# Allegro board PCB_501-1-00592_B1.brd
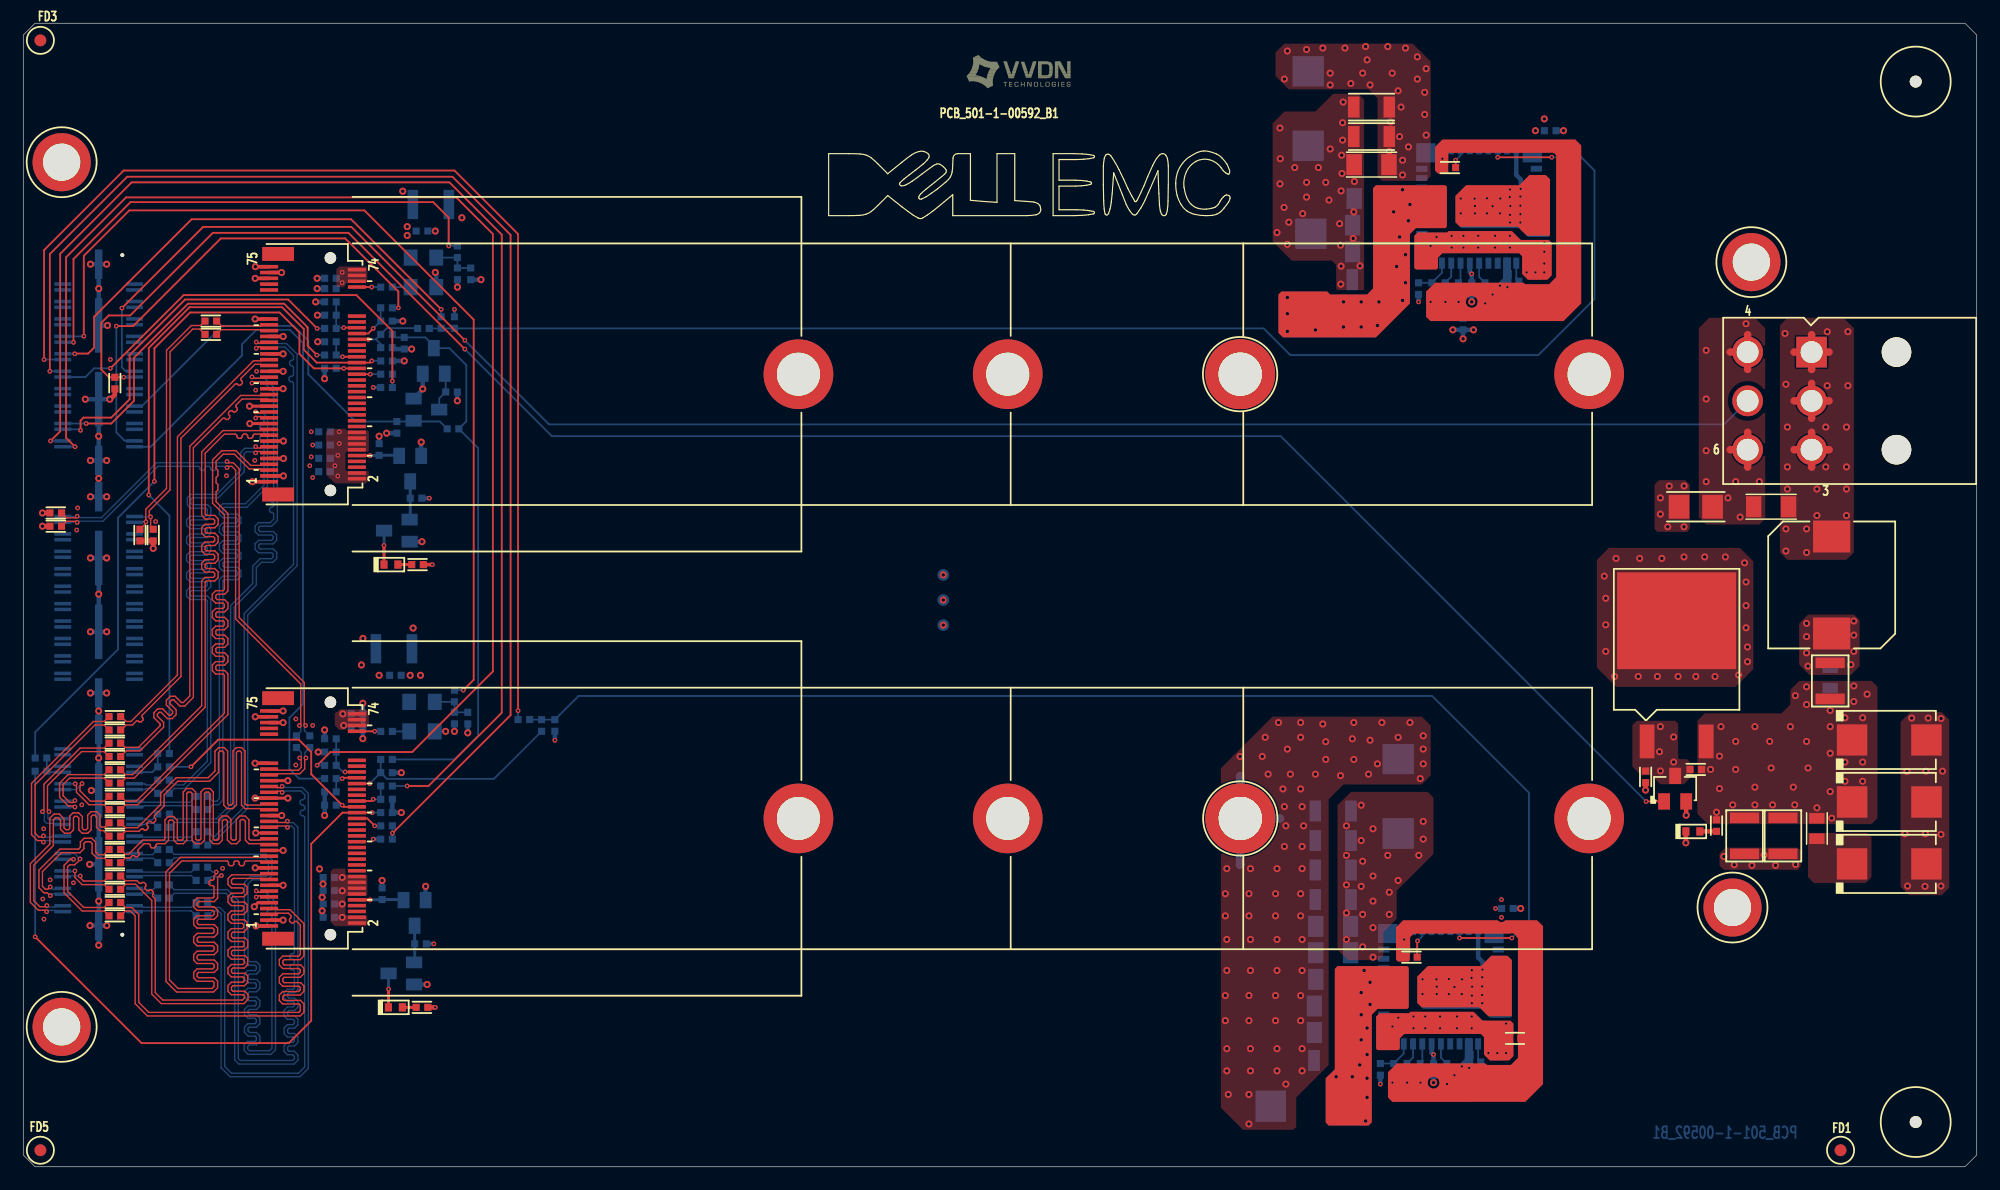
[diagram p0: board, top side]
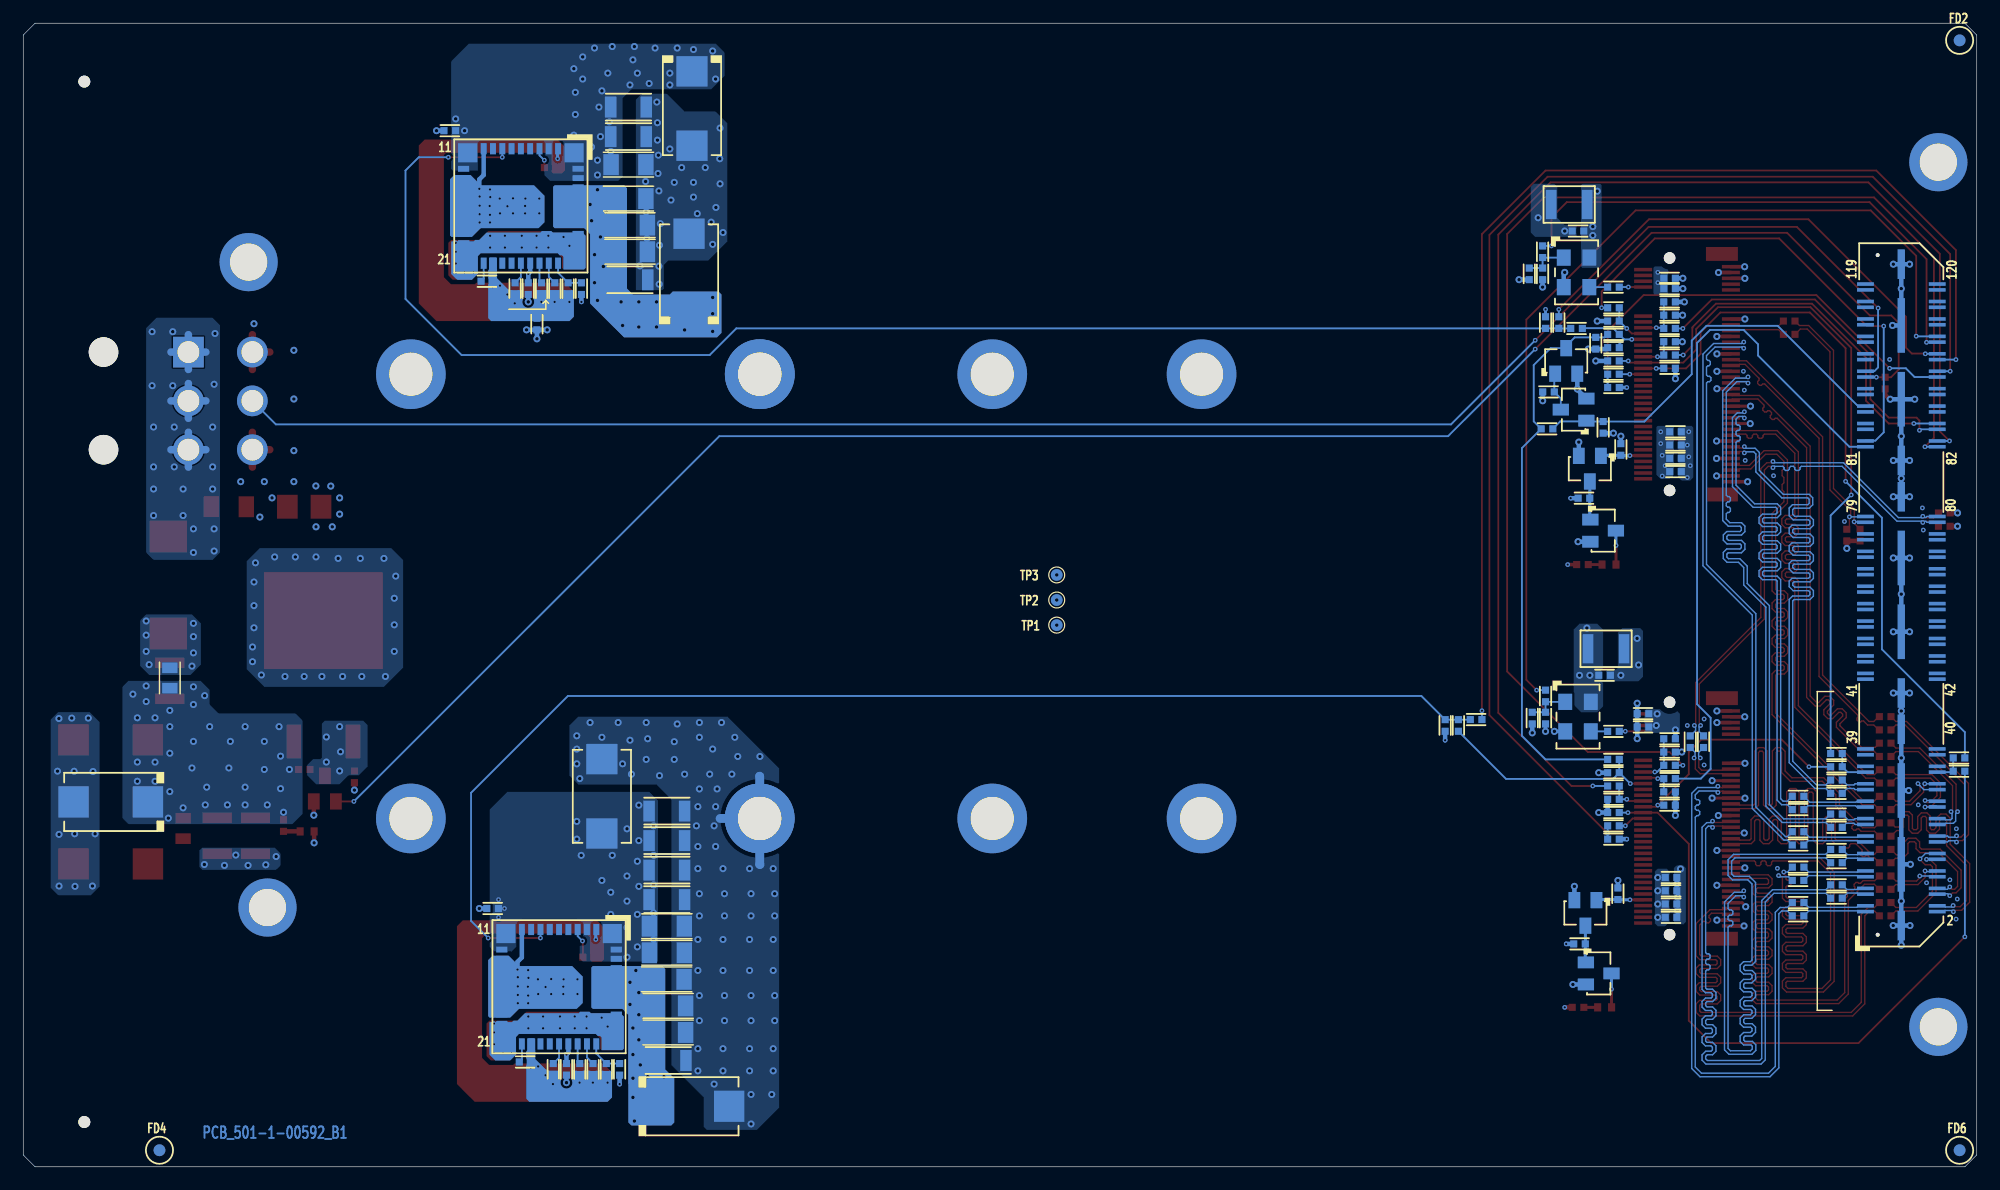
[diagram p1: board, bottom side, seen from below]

Outline 168 x 98.4 mm; copper layers: TOP, GROUND, POWER, BOTTOM. Coordinates in mm from the lower left corner of the outline.
Outline path: 0,97.38 1.02,98.4 166.98,98.4 168,97.38 168,1.02 166.98,0 1.02,0 0,1.02 0,97.38

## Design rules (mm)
constraint set DEFAULT: min track width 0.152, pair gap 0.178
net group CLK0_N: nets CLK0_N PCIE_CG1_HSMC_CLK0_N
net group CLK0_P: nets CLK0_P PCIE_CG1_HSMC_CLK0_P
net group CLK1_N: nets CLK1_N PCIE_CG1_HSMC_CLK1_N
net group CLK1_P: nets CLK1_P PCIE_CG1_HSMC_CLK1_P
net group PCIE_NVM_TX0_N: nets C_PCIE_NVM_TX0_N
net group PCIE_NVM_TX0_P: nets C_PCIE_NVM_TX0_P
net group PCIE_NVM_TX1_N: nets C_PCIE_NVM_TX1_N
net group PCIE_NVM_TX1_P: nets C_PCIE_NVM_TX1_P
net group PCIE_NVM_TX2_N: nets C_PCIE_NVM_TX2_N
net group PCIE_NVM_TX2_P: nets C_PCIE_NVM_TX2_P
net group PCIE_NVM_TX3_N: nets C_PCIE_NVM_TX3_N
net group PCIE_NVM_TX3_P: nets C_PCIE_NVM_TX3_P
net group PCIE_NVM_TX4_N: nets C_PCIE_NVM_TX4_N
net group PCIE_NVM_TX4_P: nets C_PCIE_NVM_TX4_P
net group PCIE_NVM_TX5_N: nets C_PCIE_NVM_TX5_N
net group PCIE_NVM_TX5_P: nets C_PCIE_NVM_TX5_P
net group PCIE_NVM_TX6_N: nets C_PCIE_NVM_TX6_N
net group PCIE_NVM_TX6_P: nets C_PCIE_NVM_TX6_P
net group PCIE_NVM_TX7_N: nets C_PCIE_NVM_TX7_N
net group PCIE_NVM_TX7_P: nets C_PCIE_NVM_TX7_P

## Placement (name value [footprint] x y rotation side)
C17  22uF  [1210]  31.88 44.58 180 bottom
C18  0.1uF  [0402]  32 42.29 180 bottom
C19  22uF  [1210]  35.05 82.8 0 bottom
C20  0.1uF  [0402]  34.29 80.52 0 bottom
C21  100uF  [TCAP_CASED]  160.48 36.73 0 top
C22  22uF  [1210]  148.03 28.47 270 top
C23  22uF  [1210]  151.33 28.47 270 top
C24  100uF  [TCAP_CASED]  160.48 31.39 0 top
C25  100uF  [TCAP_CASED]  160.48 31.39 0 bottom
C26  4.7uF  [1206]  112.65 18.41 180 bottom
C27  47uF  [CAP_1206]  112.65 28.07 180 bottom
C28  47uF  [CAP_1206]  112.65 30.61 180 bottom
C29  47uF  [CAP_1206]  112.65 25.53 180 bottom
C30  4.7uF  [1206]  112.65 20.7 180 bottom
C32  47uF  [CAP_1206]  112.65 22.99 180 bottom
C34  4.7uF  [1206]  112.67 16.13 180 bottom
C36  100uF  [1206]  112.54 13.84 180 bottom
C37  100uF  [1206]  112.54 11.56 180 bottom
C38  220uF  [TCAP_CASED]  110.49 5.21 180 bottom
C39  3300pF  [0402]  120.14 8.38 90 bottom
C40  0.1uF  [0402]  127.64 22.23 0 bottom
C41  0.1uF  [0402]  121.29 8.38 270 bottom
C42  47uF  [CAP_1206]  112.54 9.14 180 bottom
C43  100uF  [TCAP_CASEE]  118.24 31.88 90 bottom
C44  4.7uF  [1206]  115.95 86.23 180 top
C45  100uF  [TCAP_CASEE]  110.49 91.06 270 bottom
C46  47uF  [CAP_1206]  115.95 91.19 180 top
C47  47uF  [CAP_1206]  115.95 88.65 180 top
C48  47uF  [CAP_1206]  115.95 91.19 180 bottom
C49  47uF  [CAP_1206]  115.95 88.65 180 bottom
C50  4.7uF  [1206]  115.95 86.23 180 bottom
C51  0.1uF  [0402]  131.32 89.15 0 bottom
C52  0.1uF  [0402]  124.57 75.56 270 bottom
C53  4.7uF  [1206]  115.95 83.31 180 bottom
C54  47uF  [CAP_1206]  115.82 76.33 180 bottom
C55  100uF  [1206]  115.82 78.74 180 bottom
C56  100uF  [1206]  115.82 81.03 180 bottom
C57  220uF  [TCAP_CASED]  110.74 77.09 90 bottom
C58  3300pF  [0402]  123.43 75.56 90 bottom
C59  0.1uF  [0402]  28.7 37.85 0 bottom
C61  0.1uF  [0402]  25.91 60.96 180 bottom
C63  0.1uF  [0402]  26.29 22.61 180 bottom
C64  0.1uF  [0402]  26.29 23.75 180 bottom
C65  0.1uF  [0402]  26.29 24.89 180 bottom
C67  0.1uF  [0402]  25.91 59.82 180 bottom
C68  0.1uF  [0402]  25.91 62.1 180 bottom
C69  0.1uF  [0402]  26.42 75.56 180 bottom
C71  4.7uF  [0402]  26.29 21.46 180 bottom
C72  4.7uF  [0402]  28.7 38.99 0 bottom
C73  4.7uF  [0402]  25.91 63.25 180 bottom
C74  4.7uF  [0402]  26.42 76.45 180 bottom
C75  4.7uF  [1206]  150.32 56.79 180 top
C76  100uF  [TCAP_CASED]  160.48 26.06 0 top
D4  G  [LED-0402]  143.59 28.85 180 top
D5  G  [LED-0402]  32 13.72 180 top
D7  G  [LED-0402]  31.62 51.82 180 top
FB1  50E  [FBEAD-1206]  143.84 56.79 0 top
FD1  Local  [LFD40_80]  156.29 1.42 0 top
FD2  Local  [LFD40_80]  1.47 96.93 180 bottom
FD3  Local  [LFD40_80]  1.47 96.93 0 top
FD4  Local  [LFD40_80]  156.29 1.42 180 bottom
FD5  Local  [LFD40_80]  1.47 1.42 0 top
FD6  Local  [LFD40_80]  1.47 1.42 180 bottom
J1  CON_HSMCx3  [CON_HMSC_1X1M_132L_0P5_SM_ST]  6.49 49.21 90 bottom
J4  CON_B2C_2X3  [CON_B2C_2X3M_4P2_TH_RA_A]  153.8 70.1 90 top
J7  CON_NGFF-M  [CON_NGFF_75F_0P5_SM_RA_CST_B_A1]  26.42 29.97 90 top
J8  CON_NGFF-M  [CON_NGFF_75F_0P5_SM_RA_CST_B_A1]  26.42 68.2 90 top
L1  2.2uH  [IND2_8P34_10P1X10P1]  155.52 50.06 90 top
M1  LMZ31710  [BQFN42_0P8_10X10_EP]  121.92 15.49 270 bottom
M2  LMZ31710  [BQFN42_0P8_10X10_EP]  125.2 82.68 270 bottom
MECH1  MECH_SPACER  [MECH-M2P5_RAD3P7_C_A1]  104.67 29.97 0 top
MECH2  MECH_SPACER  [MECH-M2P5_RAD3P7_C_A1]  104.65 68.2 0 top
MH1  128MILS  [MH197D128N]  162.75 3.85 0 top
MH2  126MILS  [MH197D126]  147 22.31 0 top
MH3  126MILS  [MH197D126]  3.3 86.44 0 top
MH4  128MILS  [MH197D128N]  162.75 93.38 0 top
MH5  126MILS  [MH197D126]  3.3 12.04 0 top
MH6  126MILS  [MH197D126]  148.62 77.84 0 top
NOREF  -  []  21.14 20.72 90 top
NOREF#2  -  []  84.67 29.97 0 top
NOREF#3  -  []  21.14 34.72 90 top
NOREF#4  -  []  104.67 29.97 0 top
NOREF#5  -  []  -95.76 138.68 0 top
NOREF#6  -  []  21.14 72.95 90 top
NOREF#7  -  []  21.14 58.95 90 top
NOREF#8  -  []  21.14 58.95 90 top
NOREF#9  -  []  21.14 37.22 90 top
NOREF#10  -  []  26.42 58.2 90 top
NOREF#11  -  []  21.14 27.72 90 top
NOREF#12  -  []  21.14 20.72 90 top
NOREF#13  -  []  1.47 1.42 0 top
NOREF#14  -  []  21.14 75.45 90 top
NOREF#15  -  []  21.14 77.45 0 top
NOREF#16  -  []  104.67 68.2 0 top
NOREF#17  -  []  21.92 57.85 90 top
NOREF#18  -  []  21.14 39.22 0 top
NOREF#19  -  []  84.67 68.2 0 top
NOREF#20  -  []  66.67 29.97 90 top
NOREF#21  -  []  21.14 65.95 90 top
NOREF#22  -  []  66.67 29.97 0 top
NOREF#23  -  []  166.98 0 90 top
NOREF#24  -  []  26.42 19.97 90 top
NOREF#25  -  []  21.92 19.62 90 top
NOREF#26  -  []  66.67 68.2 90 top
NOREF#27  -  []  66.67 68.2 0 top
NOREF#28  -  []  0 97.38 0 top
Q1  SUM110P06-08L  [TO263-3L_5P08_10P29X9P65_A]  142.19 36.6 0 top
Q2  FDV301N  [SOT23-3L_1P9_3P12X1P5]  142.06 32.54 0 top
Q3  FDV301N  [SOT23-3L_1P9_3P12X1P5]  34.67 65.15 90 bottom
Q4  FDV301N  [SOT23-3L_1P9_3P12X1P5]  35.31 69.34 180 bottom
Q5  FDV301N  [SOT23-3L_1P9_3P12X1P5]  32.51 16.64 270 bottom
Q6  FDV301N  [SOT23-3L_1P9_3P12X1P5]  33.66 21.84 0 bottom
Q7  FDV301N  [SOT23-3L_1P9_3P12X1P5]  32.13 54.74 270 bottom
Q8  FDV301N  [SOT23-3L_1P9_3P12X1P5]  33.27 60.07 0 bottom
R1  0E  [0402]  7.87 25.02 180 top
R2  0E  [0402]  7.87 29.59 180 top
R3  0E  [0402]  7.87 28.45 180 top
R4  0E  [0402]  7.87 27.3 180 top
R5  0E  [0402]  7.87 26.16 180 top
R6  0E  [0402]  7.87 23.88 180 top
R7  0E  [0402]  7.87 21.59 180 top
R8  0E  [0402]  7.87 22.73 180 top
R9  0E  [0402]  7.87 38.74 180 top
R10  0E  [0402]  7.87 37.59 180 top
R11  0E  [0402]  7.87 36.45 180 top
R12  0E  [0402]  7.87 35.31 180 top
R13  0E  [0402]  7.87 34.16 180 top
R14  0E  [0402]  7.87 33.02 180 top
R15  0E  [0402]  7.87 31.88 180 top
R16  0E  [0402]  7.87 30.73 180 top
R17  0E  [0402]  1.52 34.04 180 bottom
R18  0E  [0402]  12.06 34.42 0 bottom
R19  0E  [0402_HD]  1.52 35.18 180 bottom
R20  0E  [0402]  12.06 35.56 0 bottom
R21  49.9E  [0402]  11.18 54.36 270 top
R22  49.9E  [0402]  2.79 56.26 180 top
R23  49.9E  [0402]  10.03 54.36 270 top
R24  49.9E  [0402]  2.79 55.12 180 top
R25  0E  [0402]  31.24 35.05 180 bottom
R26  0E  [0402]  31.24 71.63 180 bottom
R29  10K  [0402]  31.24 30.48 0 bottom
R30  10K  [0402]  26.42 31.11 180 bottom
R31  10K  [0402]  31.24 31.62 0 bottom
R32  10K  [0402]  31.24 33.91 0 bottom
R33  10K  [0402]  26.42 32.26 180 bottom
R34  0E  [0402]  31.24 32.77 180 bottom
R35  4.75K  [0402]  26.42 36.83 180 bottom
R36  0E  [0402]  26.42 33.4 0 bottom
R37  0E  [0402]  24.64 36.58 90 bottom
R38  0E  [0402]  26.42 34.54 0 bottom
R39  10K  [0402]  26.42 35.69 0 bottom
R40  0E  [0402]  23.49 36.58 90 bottom
R41  10K  [0402]  38.23 38.61 270 bottom
R42  10K  [0402]  37.08 38.61 90 bottom
R45  10K  [0402]  26.42 68.71 180 bottom
R46  10K  [0402]  31.24 69.34 0 bottom
R47  10K  [0402]  26.42 70.99 180 bottom
R48  10K  [0402]  31.24 70.48 0 bottom
R49  10K  [0402]  31.24 72.77 0 bottom
R50  0E  [0402]  26.42 69.85 0 bottom
R51  4.75K  [0402]  26.42 73.28 180 bottom
R52  0E  [0402]  31.24 73.91 180 bottom
R53  0E  [0402]  16.13 71.63 180 top
R54  0E  [0402]  26.42 72.14 0 bottom
R55  0E  [0402]  16.13 72.77 180 top
R56  10K  [0402]  26.42 74.42 0 bottom
R57  10K  [0402]  38.48 76.83 270 bottom
R58  10K  [0402]  37.34 76.83 90 bottom
R59  1K  [0402]  143.84 34.19 0 top
R60  1K  [0402]  145.62 29.36 90 top
R61  1K  [0402]  139.52 33.55 90 top
R62  10K  [0402]  7.87 67.44 90 top
R63  0E  [0402]  119 8.38 90 bottom
R64  316E  [0402]  122.42 8.38 270 bottom
R66  10K  [0402]  45.72 37.97 270 bottom
R67  0E  [0402]  43.05 38.48 180 bottom
R68  0E  [0402]  37.08 40.51 90 bottom
R69  0E  [0402]  37.34 78.74 90 bottom
R70  0E  [0402]  31.24 29.34 180 bottom
R71  0E  [0402]  31.24 68.2 180 bottom
R72  0E  [0402]  31.24 37.47 180 bottom
R73  0E  [0402]  31.24 75.69 180 bottom
R74  10K  [0402]  32.13 63.63 90 bottom
R75  10K  [0402]  36.83 66.67 0 bottom
R76  10K  [0402]  32.77 70.87 270 bottom
R77  0E  [0402]  36.96 63.5 0 bottom
R78  0E  [0402]  15.37 21.59 0 bottom
R79  0E  [0402]  15.36 22.73 0 bottom
R80  0E  [0402]  12.06 23.11 0 bottom
R81  0E  [0402]  12.06 24.26 0 bottom
R82  0E  [0402]  15.37 24.64 0 bottom
R83  0E  [0402]  15.36 25.78 0 bottom
R84  0E  [0402]  12.06 26.16 0 bottom
R85  0E  [0402]  12.06 27.3 0 bottom
R86  0E  [0402]  15.37 27.69 0 bottom
R87  0E  [0402]  15.37 28.83 0 bottom
R88  0E  [0402]  12.06 29.21 0 bottom
R89  0E  [0402]  12.06 30.35 0 bottom
R90  0E  [0402]  15.37 30.73 0 bottom
R91  0E  [0402]  15.37 31.88 0 bottom
R92  0E  [0402]  12.06 32.13 0 bottom
R93  0E  [0402]  12.06 33.27 0 bottom
R94  69.8E  [0402]  34.29 13.72 0 top
R95  10K  [0402]  34.16 19.18 0 bottom
R98  10K  [0402]  30.86 23.5 270 bottom
R99  10K  [0402]  31.24 28.19 180 bottom
R100  69.8E  [0402]  33.91 51.82 0 top
R101  10K  [0402]  33.78 57.53 0 bottom
R102  10K  [0402]  30.61 61.72 270 bottom
R103  10K  [0402]  31.24 67.06 180 bottom
R105  90.9K  [0402]  124.84 9.02 0 bottom
R106  9.31K  [0402]  117.86 8.38 90 bottom
R107  68.1K  [0402]  116.71 8.38 270 bottom
R108  10K  [0402]  119.38 18.03 180 top
R109  68.1K  [0402]  120 75.56 270 bottom
R110  316E  [0402]  125.7 75.56 270 bottom
R111  9.31K  [0402]  121.14 75.56 90 bottom
R112  0E  [0402]  122.28 75.56 90 bottom
R113  10K  [0402]  122.68 85.98 180 top
R114  10K  [0402]  37.08 72.64 90 bottom
R115  90.9K  [0402]  128.12 76.2 0 bottom
R116  0E  [0402]  123.83 72.52 90 bottom
R117  0E  [0402]  128.29 11.05 0 top
R118  0E  [0402]  35.94 72.64 90 bottom
R119  0E  [0402]  44.58 37.97 270 bottom
R120  0E  [0402]  34.42 72.14 180 bottom
R121  0E  [0805]  154.25 29.11 90 top
R122  0E  [0805]  155.4 42.06 90 bottom
R123  3.3E  [1210]  155.4 41.81 90 top
TP1  SMD  [TP40_SMD]  79.12 46.61 180 bottom
TP2  SMD  [TP40_SMD]  79.12 48.77 180 bottom
TP3  SMD  [TP40_SMD]  79.12 50.93 180 bottom
Y3  32.768KHz  [OSC4_2P2_5X3P2_1P35]  34.29 38.74 270 bottom
Y4  32.768KHz  [OSC4_2P2_5X3P2_1P35]  34.42 76.96 270 bottom

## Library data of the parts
C17-C20 C22 C23 C26-C30 C32 C34 C36 C37 C39-C42 C44 C46-C56 C58 C59 C61 C63-C65 C67-C69 C71-C75 = CAP_NP
C21 C24 C25 C38 C43 C45 C57 C76 = CAP_POL
D4 D5 D7 = DIODE_LED_A
FB1 = FER_BEAD
FD1-FD6 = MECH_FID_L
J1 = CONN_HSMCX3_132P_HETERO
J4 = CONN_B2C_2X3_6P_A
J7 J8 = CONN_NGFF-M_1X67_73P_CUST_A1
L1 = IND_CORE_B
M1 M2 = MODPWR_DC-DC_1OUT_42P
MECH1 MECH2 = MECH_SPACER
MH1 MH4 = MECH_MH_NPL
MH2 MH3 MH5 MH6 = MECH_MH_PL
Q1 = TRANS_PMOS-ENX1_3P_A
Q2-Q8 = TRANS_NMOS-ENX1_3P_I
R1-R16 R37 R40 R53 R55 R78-R93 = RES: signal model: RES_0402_0E_0E
R17-R26 R29-R36 R38 R39 R41 R42 R45-R52 R54 R56-R64 R66-R77 R94 R95 R98-R103 R105-R123 = RES
TP1-TP3 = TEST_POINT_SMD
Y3 Y4 = OSC_4P_A

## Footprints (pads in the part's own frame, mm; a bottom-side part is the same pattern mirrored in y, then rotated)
0402
  rect 0.61x0.61 smd: 1(-0.5,0) 2(0.5,0)
0402_HD
  rect 0.61x0.61 smd: 1(-0.5,0) 2(0.5,0)
0805
  rect 0.914x1.321 smd: 1(-0.875,0) 2(0.875,0)
1206
  rect 1.321x1.803 smd: 1(-1.5,0) 2(1.5,0)
1210
  rect 0.914x2.515 smd: 1(-1.55,0) 2(1.55,0)
BQFN42_0P8_10X10_EP
  rect 1.651x1.651 smd: 1(-4.575,4.575) 11(-4.575,-4.575) 21(4.575,-4.575) 31(4.575,4.575)
  rect 0.965x0.508 smd: 2(-4.925,3.2) 3(-4.925,2.4) 4(-4.925,1.6) 5(-4.925,0.8) 6(-4.925,0) 7(-4.925,-0.8) 8(-4.925,-1.6) 9(-4.925,-2.4) 10(-4.925,-3.2) 22(4.925,-3.2) 23(4.925,-2.4) 24(4.925,-1.6) 25(4.925,-0.8) 26(4.925,0) 27(4.925,0.8) 28(4.925,1.6) 29(4.925,2.4) 30(4.925,3.2)
  rect 0.508x0.965 smd: 12(-3.2,-4.925) 13(-2.4,-4.925) 14(-1.6,-4.925) 15(-0.8,-4.925) 16(0,-4.925) 17(0.8,-4.925) 18(1.6,-4.925) 19(2.4,-4.925) 20(3.2,-4.925) 32(3.2,4.925) 33(2.4,4.925) 34(1.6,4.925) 35(0.8,4.925) 36(0,4.925) 37(-0.8,4.925) 38(-1.6,4.925) 39(-2.4,4.925) 40(-3.2,4.925)
  rect 3.302x1.397 smd: 41(0,3.55)
  custom 0.822x0.822 smd: 42(0,-1.225)
CAP_1206
  rect 0.991x1.803 smd: 1(-1.53,0) 2(1.53,0)
CON_B2C_2X3M_4P2_TH_RA_A
  round 2.54 hole 3.073 unplated: (-8.4,-7.3) (0,-7.3)
  rect 2.642x2.642 hole 1.88: 1(0,0)
  round 2.642 hole 1.88: 2(-4.2,0) 3(-8.4,0) 4(0,5.5) 5(-4.2,5.5) 6(-8.4,5.5)
CON_HMSC_1X1M_132L_0P5_SM_ST
  round 0.33 hole 1.092 unplated: (-29.245,2.03) (29.235,2.03)
  rect 0.305x1.448 smd: 1(-27.255,3.08) 2(-27.255,-3.09) 3(-26.755,3.08) 4(-26.755,-3.09) 5(-25.755,3.08) 6(-25.755,-3.09) 7(-25.255,3.08) 8(-25.255,-3.09) 9(-24.255,3.08) 10(-24.255,-3.09) 11(-23.755,3.08) 12(-23.755,-3.09) 13(-22.755,3.08) 14(-22.755,-3.09) 15(-22.255,3.08) 16(-22.255,-3.09) 17(-21.255,3.08) 18(-21.255,-3.09) 19(-20.755,3.08) 20(-20.755,-3.09) 21(-19.755,3.08) 22(-19.755,-3.09) 23(-19.255,3.08) 24(-19.255,-3.09) 25(-18.255,3.08) 26(-18.255,-3.09) 27(-17.755,3.08) 28(-17.755,-3.09) 29(-16.755,3.08) 30(-16.755,-3.09) 31(-16.255,3.08) 32(-16.255,-3.09) 33(-15.255,3.08) 34(-15.255,-3.09) 35(-14.755,3.08) 36(-14.755,-3.09) 37(-13.755,3.08) 38(-13.755,-3.09) 39(-13.255,3.08) 40(-13.255,-3.09) 41(-7.255,3.08) 42(-7.255,-3.09) 43(-6.755,3.08) 44(-6.755,-3.09) 45(-5.755,3.08) 46(-5.755,-3.09) 47(-5.255,3.08) 48(-5.255,-3.09) 49(-4.255,3.08) 50(-4.255,-3.09) 51(-3.755,3.08) 52(-3.755,-3.09) 53(-2.755,3.08) 54(-2.755,-3.09) 55(-2.255,3.08) 56(-2.255,-3.09) 57(-1.255,3.08) 58(-1.255,-3.09) 59(-0.755,3.08) 60(-0.755,-3.09) 61(0.245,3.08) 62(0.245,-3.09) 63(0.745,3.08) 64(0.745,-3.09) 65(1.745,3.08) 66(1.745,-3.09) 67(2.245,3.08) 68(2.245,-3.09) 69(3.245,3.08) 70(3.245,-3.09) 71(3.745,3.08) 72(3.745,-3.09) 73(4.745,3.08) 74(4.745,-3.09) 75(5.245,3.08) 76(5.245,-3.09) 77(6.245,3.08) 78(6.245,-3.09) 79(6.745,3.08) 80(6.745,-3.09) 81(12.745,3.08) 82(12.745,-3.09) 83(13.245,3.08) 84(13.245,-3.09) 85(14.245,3.08) 86(14.245,-3.09) 87(14.745,3.08) 88(14.745,-3.09) 89(15.745,3.08) 90(15.745,-3.09) 91(16.245,3.08) 92(16.245,-3.09) 93(17.245,3.08) 94(17.245,-3.09) 95(17.745,3.08) 96(17.745,-3.09) 97(18.745,3.08) 98(18.745,-3.09) 99(19.245,3.08) 100(19.245,-3.09) 101(20.245,3.08) 102(20.245,-3.09) 103(20.745,3.08) 104(20.745,-3.09) 105(21.745,3.08) 106(21.745,-3.09) 107(22.245,3.08) 108(22.245,-3.09) 109(23.245,3.08) 110(23.245,-3.09) 111(23.745,3.08) 112(23.745,-3.09) 113(24.745,3.08) 114(24.745,-3.09) 115(25.245,3.08) 116(25.245,-3.09) 117(26.245,3.08) 118(26.245,-3.09) 119(26.745,3.08) 120(26.745,-3.09)
  rect 2.54x0.635 smd: 121(-28.455,0) 124(-11.565,0) 125(-8.445,0) 128(8.445,0) 129(11.565,0) 132(28.455,0)
  rect 4.699x0.635 smd: 122(-23.185,0) 123(-16.835,0) 126(-3.175,0) 127(3.175,0) 130(16.835,0) 131(23.185,0)
CON_NGFF_75F_0P5_SM_RA_CST_B_A1
  round 0.991 hole 1.118 unplated: (-10,0)
  round 0.991 hole 1.6 unplated: (10,0)
  rect 0.305x1.549 smd: 1(-9.25,5.275) 2(-9,-2.275) 3(-8.75,5.275) 4(-8.5,-2.275) 5(-8.25,5.275) 6(-8,-2.275) 7(-7.75,5.275) 8(-7.5,-2.275) 9(-7.25,5.275) 10(-7,-2.275) 11(-6.75,5.275) 12(-6.5,-2.275) 13(-6.25,5.275) 14(-6,-2.275) 15(-5.75,5.275) 16(-5.5,-2.275) 17(-5.25,5.275) 18(-5,-2.275) 19(-4.75,5.275) 20(-4.5,-2.275) 21(-4.25,5.275) 22(-4,-2.275) 23(-3.75,5.275) 24(-3.5,-2.275) 25(-3.25,5.275) 26(-3,-2.275) 27(-2.75,5.275) 28(-2.5,-2.275) 29(-2.25,5.275) 30(-2,-2.275) 31(-1.75,5.275) 32(-1.5,-2.275) 33(-1.25,5.275) 34(-1,-2.275) 35(-0.75,5.275) 36(-0.5,-2.275) 37(-0.25,5.275) 38(0,-2.275) 39(0.25,5.275) 40(0.5,-2.275) 41(0.75,5.275) 42(1,-2.275) 43(1.25,5.275) 44(1.5,-2.275) 45(1.75,5.275) 46(2,-2.275) 47(2.25,5.275) 48(2.5,-2.275) 49(2.75,5.275) 50(3,-2.275) 51(3.25,5.275) 52(3.5,-2.275) 53(3.75,5.275) 54(4,-2.275) 55(4.25,5.275) 56(4.5,-2.275) 57(4.75,5.275) 58(5,-2.275) 67(7.25,5.275) 68(7.5,-2.275) 69(7.75,5.275) 70(8,-2.275) 71(8.25,5.275) 72(8.5,-2.275) 73(8.75,5.275) 74(9,-2.275) 75(9.25,5.275)
  rect 1.194x2.743 smd: M1(-10.35,4.5) M2(10.35,4.5)
  round 5.994 hole 3.708: M3(0,-40.25) M4(0,-58.25) M5(0,-78.25) M6(0,-108.25)
FBEAD-1206
  rect 1.778x2.057 smd: 1(-1.445,0) 2(1.445,0)
IND2_8P34_10P1X10P1
  rect 2.743x3.2 smd: 1(-4.172,0) 2(4.172,0)
LED-0402
  rect 0.61x0.711 smd: 1(-0.6,0) 2(0.6,0)
LFD40_80
  round 1.016 smd: 1(0,0)
MECH-M2P5_RAD3P7_C_A1
  round 5.994 hole 3.708: 1(0,0)
MH197D126
  round 5.004 hole 3.2: 1(0,0)
MH197D128N
  round 1.016 hole 3.251: 1(0,0)
OSC4_2P2_5X3P2_1P35
  rect 1.397x1.194 smd: 1(-1.27,-1.1) 2(1.27,-1.1) 3(1.27,1.1) 4(-1.27,1.1)
SOT23-3L_1P9_3P12X1P5
  rect 1.016x1.397 smd: 1(-0.95,-1.1) 2(0.95,-1.1) 3(0,1.1)
TCAP_CASED
  rect 2.616x2.692 smd: 1(-3.2,0) 2(3.2,0)
TCAP_CASEE
  rect 2.616x2.692 smd: 1(-3.2,0) 2(3.2,0)
TO263-3L_5P08_10P29X9P65_A
  rect 1.27x2.896 smd: 1(-2.54,0) 3(2.54,0)
  rect 10.236x8.331 smd: 4(0,10.387)
TP40_SMD
  round 1.016 smd: 1(0,0)

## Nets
GND_POWER: C17.2 C18.2 C19.2 C20.2 C21.2(CATHODE) C22.2 C23.2 C24.2(CATHODE) C25.2(CATHODE) C26.2 C27.2 C28.2 C29.2 C30.2 C32.2 C34.2 C36.2 C37.2 C38.2(CATHODE) C40.2 C41.2 C42.2 C43.2(CATHODE) C44.2 C45.2(CATHODE) C46.2 C47.2 C48.2 C49.2 C50.2 C51.2 C52.2 C53.2 C54.2 C55.2 C56.2 C57.2(CATHODE) C59.2 C61.2 C63.2 C64.2 C65.2 C67.2 C68.2 C69.2 C71.2 C72.2 C73.2 C74.2 C76.2(CATHODE) D4.2(K) FB1.1 J1.121 J1.122 J1.123 J1.124 J1.125 J1.126 J1.127 J1.128 J1.129 J1.130 J1.131 J1.132(B3_PWR4) J7.1 J7.3 J7.9 J7.15 J7.21 J7.27 J7.33 J7.39 J7.45 J7.51 J7.57 J7.71 J7.73 J7.75 J7.M3 J7.M4 J7.M5 J7.M6 J8.1 J8.3 J8.9 J8.15 J8.21 J8.27 J8.33 J8.39 J8.45 J8.51 J8.57 J8.71 J8.73 J8.75 J8.M3 J8.M4 J8.M5 J8.M6 M1.20 M1.21 M1.31 M1.32 M1.33 M2.20 M2.21 M2.31 M2.32 M2.33 MH2.1 MH3.1 MH5.1 MH6.1 Q2.2(SOURCE) Q3.2(SOURCE) Q4.2(SOURCE) Q5.2(SOURCE) Q6.2(SOURCE) Q7.2(SOURCE) Q8.2(SOURCE) R21.2 R22.2 R23.2 R24.2 R39.1 R42.1 R56.1 R58.1 R61.1 R62.1 R74.1 R98.1 R102.1 R116.1 R117.1 TP2.1 Y3.2 Y4.2
GND_POWER_AUX: C75.2 FB1.2 J4.4 J4.6
SGND1: C39.1 M1.2 M1.23 R63.1 R64.2 R105.1 R106.1 R108.2 R117.2
SGND2: C58.1 M2.2 M2.23 R110.2 R111.1 R112.1 R113.2 R115.1 R116.2
VCC_3V3_A: C17.1 C18.1 C34.1 C36.1 C37.1 C38.1 C41.1 C42.1 C59.1 C63.1 C64.1 C65.1 C71.1 C72.1 J7.2 J7.4 J7.12 J7.14 J7.16 J7.18 J7.70 J7.72 J7.74 M1.27 M1.34 M1.35 M1.36 M1.37 M1.38 M1.41(VOUT6) R29.2 R30.2 R31.2 R32.2 R33.2 R35.2 R41.2 R66.2 R94.2 R95.2 R99.2 TP1.1 Y3.4(VDD)
VCC_3V3_B: C19.1 C20.1 C52.1 C53.1 C54.1 C55.1 C56.1 C57.1 C61.1 C67.1 C68.1 C69.1 C73.1 C74.1 J8.2 J8.4 J8.12 J8.14 J8.16 J8.18 J8.70 J8.72 J8.74 M2.27 M2.34 M2.35 M2.36 M2.37 M2.38 M2.41(VOUT6) R45.2 R46.2 R47.2 R48.2 R49.2 R51.2 R57.2 R75.2 R76.2 R100.2 R101.2 R103.2 R114.2 TP3.1 Y4.4(VDD)
VCC_12V0: C26.1 C27.1 C28.1 C29.1 C30.1 C32.1 C40.1 C43.1 C44.1 C45.1 C46.1 C47.1 C48.1 C49.1 C50.1 C51.1 M1.1 M1.3 M1.11 M1.12 M1.39 M1.40 M2.1 M2.3 M2.11 M2.12 M2.39 M2.40 Q1.4 R107.2 R109.2
VCC_12V_AUX: C75.1 J4.1 J4.2 J4.3 L1.2
C_PCIE_NVM_RX0_N: J1.4 R3.2
C_PCIE_NVM_RX0_P: J1.2 R2.2
C_PCIE_NVM_RX1_N: J1.8 R5.2
C_PCIE_NVM_RX1_P: J1.6 R4.2
C_PCIE_NVM_RX2_N: J1.12 R6.2
C_PCIE_NVM_RX2_P: J1.10 R1.2
C_PCIE_NVM_RX3_N: J1.16 R8.2
C_PCIE_NVM_RX3_P: J1.14 R7.2
C_PCIE_NVM_RX4_N: J1.20 R10.2
C_PCIE_NVM_RX4_P: J1.18 R9.2
C_PCIE_NVM_RX5_N: J1.24 R12.2
C_PCIE_NVM_RX5_P: J1.22 R11.2
C_PCIE_NVM_RX6_N: J1.28 R14.2
C_PCIE_NVM_RX6_P: J1.26 R13.2
C_PCIE_NVM_RX7_N: J1.32 R16.2
C_PCIE_NVM_RX7_P: J1.30 R15.2
C_PCIE_NVM_TX0_N: J1.3 R79.1
C_PCIE_NVM_TX0_P: J1.1 R78.1
C_PCIE_NVM_TX1_N: J1.7 R81.1
C_PCIE_NVM_TX1_P: J1.5 R80.1
C_PCIE_NVM_TX2_N: J1.11 R83.1
C_PCIE_NVM_TX2_P: J1.9 R82.1
C_PCIE_NVM_TX3_N: J1.15 R85.1
C_PCIE_NVM_TX3_P: J1.13 R84.1
C_PCIE_NVM_TX4_N: J1.19 R87.1
C_PCIE_NVM_TX4_P: J1.17 R86.1
C_PCIE_NVM_TX5_N: J1.23 R89.1
C_PCIE_NVM_TX5_P: J1.21 R88.1
C_PCIE_NVM_TX6_N: J1.27 R91.1
C_PCIE_NVM_TX6_P: J1.25 R90.1
C_PCIE_NVM_TX7_N: J1.31 R93.1
C_PCIE_NVM_TX7_P: J1.29 R92.1
CLK0_N: J7.53 R37.1
CLK0_P: J7.55 R40.1
CLK1_N: J8.53 R53.1
CLK1_P: J8.55 R55.1
CLK_32KHZ_1: R72.1 Y3.3
CLK_32KHZ_2: R73.1 Y4.3
CLKREQ#_1: J1.81 R36.1
CLKREQ#_2: J1.83 R52.1
DAS/LED2: J8.10 Q8.1 R102.2
DAS/LED_1: J7.10 Q6.1 R98.2
DEVSLP_1: J1.100 R70.1 R99.1
DEVSLP_2: J1.98 R71.1 R103.1
HSMC_PWR_SENSE: J1.99 J4.5
HSMC_RESET#: J1.91 Q3.1 R74.2 R77.1
OSC1_EN: J1.108 R68.2
OSC2_EN: J1.106 R69.2
P_12V_HSMC_ON: J1.97 Q2.1 R62.2
P_12V_ON: Q1.1 Q2.3 R59.1 R61.2
PCIE1_SMBUS_ALERT: J1.84 R34.1
PCIE1_SMBUS_SCL: J7.40 R17.2 R29.1
PCIE1_SMBUS_SDA: J7.42 R18.2 R30.1
PCIE1_WAKE#: J7.54 R35.1 R38.2 R39.2
PCIE1_WAKE#_HSE: J1.82 R38.1
PCIE2_SMBUS_ALERT: J1.88 R50.1
PCIE2_SMBUS_SCL: J8.40 R19.2 R45.1
PCIE2_SMBUS_SDA: J8.42 R20.2 R46.1
PCIE2_WAKE#: J8.54 R51.1 R54.2 R56.2
PCIE2_WAKE#_HSE: J1.86 R54.1
PCIE_CG1_HSMC_CLK0_N: J1.80 R22.1 R37.2
PCIE_CG1_HSMC_CLK0_P: J1.78 R24.1 R40.2
PCIE_CG1_HSMC_CLK1_N: J1.79 R21.1 R53.2
PCIE_CG1_HSMC_CLK1_P: J1.77 R23.1 R55.2
PCIE_NVM_RX0_N: J7.41 R3.1
PCIE_NVM_RX0_P: J7.43 R2.1
PCIE_NVM_RX1_N: J7.29 R5.1
PCIE_NVM_RX1_P: J7.31 R4.1
PCIE_NVM_RX2_N: J7.17 R6.1
PCIE_NVM_RX2_P: J7.19 R1.1
PCIE_NVM_RX3_N: J7.5 R8.1
PCIE_NVM_RX3_P: J7.7 R7.1
PCIE_NVM_RX4_N: J8.41 R10.1
PCIE_NVM_RX4_P: J8.43 R9.1
PCIE_NVM_RX5_N: J8.29 R12.1
PCIE_NVM_RX5_P: J8.31 R11.1
PCIE_NVM_RX6_N: J8.17 R14.1
PCIE_NVM_RX6_P: J8.19 R13.1
PCIE_NVM_RX7_N: J8.5 R16.1
PCIE_NVM_RX7_P: J8.7 R15.1
PCIE_NVM_TX0_N: J7.47 R79.2
PCIE_NVM_TX0_P: J7.49 R78.2
PCIE_NVM_TX1_N: J7.35 R81.2
PCIE_NVM_TX1_P: J7.37 R80.2
PCIE_NVM_TX2_N: J7.23 R83.2
PCIE_NVM_TX2_P: J7.25 R82.2
PCIE_NVM_TX3_N: J7.11 R85.2
PCIE_NVM_TX3_P: J7.13 R84.2
PCIE_NVM_TX4_N: J8.47 R87.2
PCIE_NVM_TX4_P: J8.49 R86.2
PCIE_NVM_TX5_N: J8.35 R89.2
PCIE_NVM_TX5_P: J8.37 R88.2
PCIE_NVM_TX6_N: J8.23 R91.2
PCIE_NVM_TX6_P: J8.25 R90.2
PCIE_NVM_TX7_N: J8.13 R93.2
PCIE_NVM_TX7_P: J8.11 R92.2
PERST1#: J7.50 R25.2 R32.1 R119.2
PERST2#: J8.50 R26.2 R48.1 R120.2
PGOOD_3V3_A: M1.8 R66.1 R67.1 R119.1
PGOOD_3V3_B: M2.8 R114.1 R118.1 R120.1
PWR_RST#: J1.89
PWR_RST#_COMM: Q4.3 R25.1 R26.1 R76.1 R77.2
SS/TR_3V3_A: C39.2 M1.28
SS/TR_3V3_B: C58.2 M2.28
STSEL_3V3_A: M1.29 R63.2
STSEL_3V3_B: M2.29 R112.2
UVLO_1: M1.30 R106.2 R107.1
UVLO_2: M2.30 R109.1 R111.2
VADJ_3V3_A: M1.26 R64.1
VADJ_3V3_B: M2.26 R110.1
N2986241: J1.34 R17.1 R19.1
N16765591: D4.1 R60.1
N16765603: C21.1 C22.1 C23.1 C24.1 C25.1 Q1.3(SOURCE) R59.2 R60.2 R121.2 R122.1 R123.1
N19373667: J1.33 R18.1 R20.1
N19381543: J7.52 R33.1 R36.2
N19381958: J8.52 R49.1 R52.2
N19382544: J7.44 R31.1 R34.2
N19383230: J8.44 R47.1 R50.2
N19387719: R41.1 R42.2 R68.1 Y3.1
N19387935: R57.1 R58.2 R69.1 Y4.1
N19416578: J7.38 R70.2
N19421657: J8.38 R71.2
N19429194: J7.68(SUSCLK) R72.2
N19429230: J8.68(SUSCLK) R73.2
N19444474: Q3.3 Q4.1 R75.1
N19453893: Q5.1 Q6.3 R95.1
N19454725: D5.1 R94.1
N19454731: D5.2(K) Q5.3
N19455675: D7.1 R100.1
N19455677: Q7.1 Q8.3 R101.1
N19455687: D7.2(K) Q7.3
N19467364: M1.10 M1.13 M1.14 M1.15 M1.16 M1.17 M1.18 M1.19 M1.42
N19467701: M1.22 R105.2
N19470945: M1.4 R108.1
N19472498: M2.10 M2.13 M2.14 M2.15 M2.16 M2.17 M2.18 M2.19 M2.42
N19472885: M2.4 R113.1
N19472919: M2.22 R115.2
N19474380: J1.102 R67.2
N19474383: J1.104 R118.2
N19510410: C76.1 R121.1
N19528011: L1.1 R122.2 R123.2

Pads without a net: FD1 1; FD2 1; FD3 1; FD4 1; FD5 1; FD6 1; J1 35 36 37 38 39 40 41 42 43 44 45 46 47 48 49 50 51 52 53 54 55 56 57 58 59 60 61 62 63 64 65 66 67 68 69 70 71 72 73 74 75 76 85 87 90 92 93 94 95 96 101 103 105 107 109 110 111 112 113 114 115 116 117 118 119 120; J7 6 8 20 22 24 26 28 30 32 34 36 46 48 56 58 67 69 M1 M2; J8 6 8 20 22 24 26 28 30 32 34 36 46 48 56 58 67 69 M1 M2; M1 5 6 7 9 24 25; M2 5 6 7 9 24 25; MECH1 1; MECH2 1; MH1 1; MH4 1

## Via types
v1: diameter 0.61, hole 0.305, TOP to BOTTOM, 442 vias
v2: diameter 0.406, hole 0.203, TOP to BOTTOM, 236 vias

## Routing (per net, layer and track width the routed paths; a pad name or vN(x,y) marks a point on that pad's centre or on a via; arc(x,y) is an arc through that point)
GND_POWER: length 252.6
  TOP w0.203: J7.27 v1(22.35,27.22) ; J7.33 v1(20,28.72)
  TOP w0.254: v1(19.87,22.38) 19.87,22.42 20.17,22.72 J7.9 ; J8.27 v1(19.46,65.45) ; J7.51 v1(22.76,33.22) ; J7.45 v1(22.76,31.72) ; J8.21 v1(19.48,63.95)
  TOP w0.305: J8.75 v1(19.96,77.45) ; J7.75 v1(22.35,39.22) ; J7.15 v1(22.35,24.22) ; J7.73 v1(19.95,38.72) ; J7.39 22.22,30.22 v1(22.22,30.23) ; J8.57 v1(19.94,72.95) ; J8.73 v1(22.21,76.95) ; J8.9 v1(22.38,60.95) ; J8.71 v1(19.94,76.45) ; J8.1 v1(19.71,58.95) ; J8.33 22.3,66.95 22.3,66.95 v1(22.35,66.95) ; J7.21 v1(19.95,25.72) ; J7.57 v1(19.93,34.72) ; v1(19.93,31.72) J7.45 ; J8.39 v1(22.35,68.45) ; J8.15 v1(22.37,62.45) ; J8.3 v1(22.37,59.45) ; J7.71 v1(22.35,38.22) ; J7.1 v1(20.02,20.72) ; J8.51 v1(22.35,71.45) ; J8.45 v1(22.35,69.95) ; J7.3 v1(22.35,21.22)
  TOP w0.381: R24.2 v1(1.65,55.12) ; Q2.2 v1(143.01,30.25) ; R62.1 7.87,66.43 7.49,66.05 v1(7.44,66.05) ; R61.1 v1(139.52,32.41) ; D4.2 v1(142.99,27.87) ; R22.2 v1(1.65,56.26) ; v1(11.18,53.21) R21.2 R23.2
  GROUND w0.635: J8.M4 84.67,70.38 ; J8.M4 82.48,68.2 ; J8.M4 86.85,68.2 ; J8.M4 84.67,66.01 ; 0.62,86.44 MH3.1 ; MH3.1 3.3,83.76 ; MH3.1 5.98,86.44 ; MH3.1 3.3,89.12 ; 132.48,29.97 J7.M6 ; J7.M6 134.67,27.79 ; J7.M6 134.67,32.16 ; J7.M6 136.85,29.97 ; 134.67,66.01 J8.M6 ; J8.M6 132.48,68.2 ; J8.M6 134.67,70.38 ; J8.M6 136.85,68.2 ; 66.67,66.01 J8.M3 ; J8.M3 66.67,70.38 ; J8.M3 64.48,68.2 ; J8.M3 68.85,68.2 ; 66.67,27.79 J7.M3 ; J7.M3 64.48,29.97 ; J7.M3 68.85,29.97 ; J7.M3 66.67,32.16 ; J7.M4 86.85,29.97 ; J7.M4 84.67,27.79 ; J7.M4 82.48,29.97 ; J7.M4 84.67,32.16 ; MH5.1 3.3,14.72 ; MH5.1 5.98,12.04 ; MH5.1 0.62,12.04 ; MH5.1 3.3,9.36 ; 144.32,22.31 MH2.1 ; MH2.1 147,19.63 ; MH2.1 147,24.99 ; MH2.1 149.68,22.31 ; MH6.1 148.62,80.52 ; MH6.1 148.62,75.16 ; MH6.1 151.3,77.84 ; MH6.1 145.94,77.84
  GROUND w0.762: 100.73,68.37 104.5,68.37 J8.M5 ; 104.81,71.65 104.81,68.35 104.76,68.29 ; 104.8,64.53 104.8,68.06 J8.M5 ; 104.76,68.29 J8.M5 ; 104.76,68.29 108.66,68.29
  POWER w0.635: 3.3,9.36 MH5.1 ; MH5.1 3.3,14.72 ; MH5.1 5.98,12.04
  BOTTOM w0.305: Y3.2 v1(36.32,37.47) ; R42.1 v1(37.08,37.47)
  BOTTOM w0.381: J1.129 v1(5.78,60.78) ; J1.129 v1(6.49,62.87) J1.130 ; J1.129 v1(7.17,60.78) ; J1.129 v1(6.49,59.23) J1.128 ; J1.128 v1(7.17,57.66) ; J1.128 v1(5.78,57.66) ; C52.2 v1(124.57,74.42) ; R116.1 v1(124.72,72.02) ; R116.1 v1(122.94,72.02) ; R116.1 v1(123.83,71.25) ; C41.2 v1(121.29,7.24) ; Q5.2 v1(34.73,15.69) ; J1.130 v1(7.44,66.05) ; J1.130 v1(5.33,66.05) ; J1.121 v1(6.49,19.06) ; J1.121 v1(7.18,20.76) ; J1.121 v1(5.74,20.76) ; J1.121 v1(6.49,22.86) J1.122 ; J1.125 v1(7.17,40.77) ; J1.125 v1(5.78,40.77) ; J1.125 v1(6.49,39.22) J1.124 v1(6.49,35.18) J1.123 ; J1.122 J1.123 ; J1.122 v1(5.71,26.03) ; Q3.2 34.36,66.89 v1(34.36,66.93) Q4.2 ; J1.123 v1(5.85,32.38) ; J1.126 v1(6.49,49.28) J1.127 ; J1.126 v1(5.78,46.04) ; J1.126 v1(7.17,46.04) ; R58.1 v1(37.34,75.69) ; C40.2 v1(128.78,22.23) ; v1(7.25,72.4) J1.131 v1(6.49,75.56) J1.132 ; v1(35.43,76.96) 35.52,76.88 Y4.2 ; Q8.2 v1(34.22,62.36) ; Q6.2 v1(34.6,24.13) ; R74.1 v1(31.25,63.13) ; R39.1 v1(25.37,35.69) ; v1(29.2,36.84) C59.2 C72.2 v1(29.2,39.89) ; R102.1 v1(30.61,62.87) ; Q7.2 v1(34.29,53.79) ; J1.127 v1(5.78,52.39) ; J1.127 v1(7.17,52.39) ; C69.2 v1(25.27,75.56) ; J1.132 v1(7.17,77.67) ; J1.132 v1(5.78,77.67) ; R98.1 v1(30.86,24.64) ; C74.2 v1(25.27,76.45) ; C51.2 v1(132.46,89.15) ; R56.1 v1(25.15,74.42)
  BOTTOM w0.762: 104.68,33.6 104.67,33.59 J7.M5 ; J7.M5 104.67,26.02 104.65,26 ; J7.M5 108.07,29.97
  vias: v1(25.48,25.63) v1(25.7,23.19) v1(25.7,22.02) v1(25.78,24.33) v1(29.08,43.18) v1(29.21,45.47) v1(30.61,42.29) v1(35.43,80.52) v1(37.72,81.66) v1(79.12,48.77) v1(103.38,23.5) v1(103.38,21.59) v1(103.38,14.73) v1(103.38,12.57) v1(103.51,25.65) v1(103.51,19.56) v1(103.51,16.89) v1(103.51,10.16) v1(103.51,8.26) v1(103.63,6.22) v1(104.65,35.31) v1(105.41,23.5) v1(105.41,21.59) v1(105.41,14.73) v1(105.41,12.57) v1(105.41,6.22) v1(105.41,3.68) v1(105.54,25.65) v1(105.54,19.56) v1(105.54,16.89) v1(105.54,10.16) v1(105.54,8.26) v1(106.55,35.31) v1(106.81,36.96) v1(107.06,33.78) v1(107.7,23.5) v1(107.7,21.59) v1(107.7,14.73) v1(107.7,12.57) v1(107.82,80.39) v1(107.82,25.65) v1(107.82,19.56) v1(107.82,16.89) v1(107.82,10.16) v1(107.82,8.26) v1(107.95,38.23) v1(108.08,89.38) v1(108.1,86.74) v1(108.08,84.58) v1(108.33,32.51) v1(108.43,82.55) v1(108.46,30.99) v1(108.46,27.56) v1(108.59,29.34) v1(108.59,7.11) v1(108.71,79.38) v1(108.71,35.94) v1(108.84,81.28) v1(108.97,33.78) v1(109.35,85.98) v1(109.86,38.23) v1(109.86,36.96) v1(109.86,32.51) v1(109.86,23.5) v1(109.86,21.59) v1(109.86,14.73) v1(109.86,12.57) v1(109.98,30.99) v1(109.98,27.56) v1(109.98,25.65) v1(109.98,19.56) v1(109.98,16.89) v1(109.98,10.16) v1(109.98,8.26) v1(110.03,82.02) v1(110.11,29.34) v1(110.36,84.71) v1(110.36,83.44) v1(111.12,33.78) v1(111.38,85.98) v1(111.76,38.1) v1(112.01,84.71) v1(112.01,36.58) v1(112.01,35.05) v1(112.29,83.19) v1(112.4,87.58) v1(113.21,81.15) v1(113.28,79.3) v1(113.31,75.95) v1(113.28,33.66) v1(113.39,87.05) v1(113.41,85.47) v1(113.33,83.97) v1(113.33,77.5) v1(113.51,91.62) v1(113.46,89.84) v1(113.46,88.34) v1(114.3,36.83) v1(114.38,79.88) v1(114.48,84.79) v1(114.43,82.17) v1(114.43,38.23) v1(114.43,35.05) v1(114.96,77.52) v1(115.7,33.78) v1(115.82,36.7) v1(116.46,34.67) v1(116.84,38.23) v1(118.24,36.96) v1(119.25,38.23) v1(120.14,33.4) v1(120.4,37.08) v1(120.4,35.94) v1(120.4,34.67) v1(140.79,57.56) v1(140.79,56.16) v1(141.43,55.07) v1(141.55,58.57) v1(142.84,58.58) v1(142.82,55.07) v1(146.25,26.7) v1(147.14,25.98) v1(148.67,25.93) v1(149.72,26.82) v1(150.7,25.93) v1(152.43,26.01) v1(161.82,28.65) v1(162,34.01) v1(162.05,24.16) v1(162.41,38.61) v1(163.58,28.65) v1(163.55,24.13) v1(163.63,34.04) v1(163.83,38.61) v1(164.92,28.6) v1(164.92,24.16) v1(164.93,38.57) v1(165.06,34.04) v2(1.68,23.04) v2(1.75,29.08) v2(1.78,21.31) v2(2.31,24.69) v2(4.32,24.43) v2(4.6,54.79) v2(4.67,56.69) v2(5.03,31.14) v2(7.49,69.47) v2(11.38,55.52) v2(17.14,25.68) v2(17.48,59.46) v2(19.91,60.78) v2(19.99,66.83) v2(20.07,68.45) v2(23.44,38.53) v2(23.44,34.57) v2(24.64,60.33) v2(24.76,63.25) v2(24.76,61.09) v2(24.89,62.1) v2(24.89,59.31) v2(24.89,37.97) v2(117.75,12.06) v2(118.26,12.83) v2(119.56,12.93) v2(119.56,11.91) v2(120.57,12.93) v2(120.57,11.91) v2(121.03,79.25) v2(121.54,80.01) v2(121.84,12.93) v2(121.84,11.91) v2(122.84,80.11) v2(122.84,79.1) v2(123.3,12.93) v2(123.3,11.91) v2(123.86,80.11) v2(123.86,79.1) v2(124.57,12.93) v2(124.57,11.91) v2(125.13,80.11) v2(125.13,79.1) v2(126,9.78) v2(126.58,80.11) v2(126.58,79.1) v2(126.76,9.78) v2(127.53,12.32) v2(127.53,11.56) v2(127.53,10.54) v2(127.53,9.78) v2(127.85,80.11) v2(127.85,79.1) v2(129.29,76.96) v2(130.05,76.96) v2(130.81,79.5) v2(130.81,78.74) v2(130.81,77.72) v2(130.81,76.96)
GND_POWER_AUX: length 19.2
  TOP w0.635: 146.8,61.7 J4.6 ; J4.6 148.3,63.2 ; J4.6 148.3,60.2 ; 146.8,70.1 J4.4 ; J4.4 148.3,68.6 ; J4.4 148.3,71.6
  GROUND w0.635: 147.03,70.1 J4.4 ; J4.4 148.3,68.83 ; J4.4 148.3,71.37 ; J4.4 149.57,70.1 ; 147.03,61.7 J4.6 ; J4.6 148.3,62.97 ; J4.6 148.3,60.43 ; J4.6 149.57,61.7
  vias: v1(144.73,70.26) v1(144.73,66.07) v1(144.73,61.62) v1(144.73,58.95) v1(146.61,57.56) v1(147.27,58.95) v1(147.65,55.91) v1(148.16,72.54) v1(149.3,58.95)
SGND1: length 0.9
  BOTTOM w0.254: M1.2 118.77,20.37 118.77,19.69 118.76,19.68 v2(118.76,19.56)
  BOTTOM w0.381: 124.32,9.04 R105.1
  vias: v2(117.75,7.24) v2(119.02,7.24) v2(120.16,7.24) v2(122.45,7.11) v2(123.08,7.87) v2(123.72,8.64) v2(124.35,8.51)
SGND2: length 0.9
  BOTTOM w0.254: v2(122.05,86.74) 122.05,86.87 122.05,86.87 122.05,87.56 M2.2
  vias: v2(121.03,74.42) v2(122.3,74.42) v2(123.44,74.42) v2(125.73,74.3) v2(126.37,75.06) v2(127,75.82) v2(127.64,75.69)
VCC_3V3_A: length 16.4
  TOP w0.381: R94.2 v2(35.43,13.72)
  POWER w0.381: v2(121.29,9.65) v1(115.57,9.65)
  BOTTOM w0.381: C41.1 v2(121.29,9.65) 121.12,9.82 M1.27 ; R33.2 R30.2 v1(25.92,30.23) ; R35.2 v1(25.92,37.59) ; R31.2 R29.2 v1(32.51,30.48) ; R66.2 v2(45.72,36.7) ; R41.2 v1(38.23,37.34) ; R95.2 v2(35.31,19.18) ; R32.2 v1(32.51,33.91) ; R99.2 v2(30.1,28.19)
  vias: v1(27.48,38.97) v1(27.43,24.89) v1(27.43,23.75) v1(27.43,22.61) v1(27.43,21.46) v1(27.56,37.97) v1(33.27,42.29) v1(33.53,46.36) v1(34.16,42.29) v1(79.12,46.61) v1(112.9,7.75) v1(114.3,7.75) v1(114.94,8.76) v1(115.06,14.99) v1(115.06,13.08) v1(115.06,10.92) v1(115.32,16.89) v1(115.44,3.94) v1(115.57,11.94) v1(115.57,7.62) v1(115.57,5.97) v1(115.82,15.88) v1(115.82,13.97)
VCC_3V3_B: length 17
  TOP w0.305: R100.2 v2(35.18,51.82)
  POWER w0.381: v2(124.57,76.83) 119.38,76.83
  BOTTOM w0.254: R114.2 v2(37.08,73.78)
  BOTTOM w0.305: R103.2 v2(30.1,67.06)
  BOTTOM w0.381: R48.2 31.86,70.37 R76.2 v1(33.4,70.37) ; C52.1 v2(124.57,76.83) 124.4,77 M2.27 ; R101.2 v2(34.92,57.53) ; R46.2 v1(32.77,69.34) ; R75.2 v1(37.33,65.91) ; R57.2 v1(39.36,76.33) ; R47.2 v1(25.32,70.99) ; R49.2 v1(32.64,72.77) ; R45.2 v1(25.92,67.81) ; R51.2 v1(25.3,73.28)
  vias: v1(32.64,83.95) v1(33.02,80.9) v1(33.02,80.14) v1(79.12,50.93) v1(108.71,74.8) v1(108.71,73.41) v1(108.71,71.88) v1(111.12,72.01) v1(113.54,74.42) v1(113.54,72.26) v1(115.06,74.42) v1(115.06,72.26) v1(116.46,72.39) v1(116.59,74.42) v1(117.86,82.17) v1(118.11,77.47) v1(118.36,80.01) v1(118.62,84.07) v1(118.62,74.55) v1(118.87,78.49) v1(118.87,76.07) v1(119.13,81.41) v1(119.25,82.8) v2(26.8,60.33) v2(27.05,61.21) v2(27.05,59.44) v2(27.18,63.25) v2(27.18,62.23) v2(27.43,76.97) v2(27.43,76.08)
VCC_12V0: length 1.4
  BOTTOM w0.381: R109.2 v2(120,74.42) ; R107.2 v2(116.71,7.11)
  vias: v1(108.46,93.6) v1(108.71,96.01) v1(110.36,96.14) v1(111.76,96.27) v1(112.4,94.11) v1(112.4,93.09) v1(113.67,96.27) v1(113.79,29.34) v1(113.79,26.8) v1(113.79,24.26) v1(113.79,21.84) v1(113.79,19.56) v1(114.17,93.22) v1(115.06,31.11) v1(115.06,28.07) v1(115.06,24.13) v1(115.19,94.11) v1(115.19,26.29) v1(115.19,21.72) v1(115.19,18.92) v1(115.44,96.39) v1(115.57,95.25) v1(115.82,93.09) v1(116.08,29.08) v1(116.08,25.02) v1(116.08,22.86) v1(116.08,20.57) v1(116.08,18.03) v1(117.35,96.39) v1(117.35,26.8) v1(117.48,87.38) v1(117.48,23.62) v1(117.48,21.72) v1(117.6,89.92) v1(117.73,94.11) v1(118.24,92.58) v1(118.24,24.64) v1(118.36,88.65) v1(118.49,91.19) v1(118.62,86.61) v1(118.62,85.34) v1(118.87,96.27) v1(119.13,87.76) v1(119.89,95.5) v1(119.89,93.6) v1(120.02,26.8) v1(120.4,29.72) v1(120.4,28.19) v1(120.52,92.46) v1(120.52,90.55) v1(120.65,94.49) v1(120.65,88.77) v1(130.05,89.15) v1(130.81,90.17) v1(135.97,50.83) v1(136.09,48.92) v1(136.09,46.63) v1(136.09,44.35) v1(136.86,42.19) v1(136.98,52.35) v1(138.89,42.19) v1(139.01,52.35) v1(140.54,42.19) v1(140.92,52.35) v1(142.32,42.19) v1(142.82,52.48) v1(143.84,42.19) v1(144.6,52.48) v1(145.49,42.19) v1(146.38,52.48) v1(147.52,42.32) v1(148.03,51.97) v1(148.16,50.32) v1(148.16,48.29) v1(148.16,46.38) v1(148.29,44.73) v1(148.29,43.46) v2(126.62,22.23) v2(127.13,22.99) v2(127.13,21.46)
VCC_12V_AUX: length 51.2
  TOP w0.635: J4.3 153.8,63.2 ; J4.3 153.8,60.2 ; J4.3 152.3,61.7 ; J4.3 155.3,61.7 ; 153.8,64.41 J4.2 ; J4.2 155.3,65.9 ; J4.2 152.3,65.9 ; J4.2 153.8,67.4 ; J4.1 153.8,71.6 ; J4.1 155.3,70.1 ; J4.1 153.8,68.6 ; J4.1 152.3,70.1
  POWER w0.635: J4.2 153.8,67.17 ; J4.2 152.53,65.9 ; J4.2 155.07,65.9 ; J4.2 153.8,64.63 ; 153.8,68.83 J4.1 ; J4.1 152.53,70.1 ; J4.1 153.8,71.37 ; J4.1 155.07,70.1 ; J4.3 155.07,61.7 ; J4.3 153.8,62.97 ; J4.3 153.8,60.43 ; J4.3 152.53,61.7
  BOTTOM w0.635: 153.8,60.2 J4.3 ; J4.3 152.3,61.7 ; J4.3 155.3,61.7 ; J4.3 153.8,63.2 ; J4.1 155.3,70.1 ; J4.1 153.8,71.6 ; J4.1 153.8,68.6 ; J4.1 152.3,70.1 ; 153.8,64.41 J4.2 ; J4.2 153.8,67.4 ; J4.2 155.3,65.9 ; J4.2 152.3,65.9
  vias: v1(151.51,71.7) v1(151.59,67.34) v1(151.59,54.89) v1(151.59,52.98) v1(151.71,63.65) v1(151.71,60.22) v1(151.71,58.32) v1(153.37,54.89) v1(153.37,52.86) v1(154.25,58.32) v1(154.25,56.04) v1(155.02,63.65) v1(155.02,60.22) v1(155.14,71.86) v1(155.14,67.21) v1(156.79,63.65) v1(156.79,60.22) v1(156.79,58.32) v1(156.79,56.04) v1(156.92,71.86) v1(156.92,67.21)
C_PCIE_NVM_RX0_N: length 21.4
  TOP w0.114: R3.2 6.89,28.93 6.59,28.93 6.3,29.22 6.3,30.14 6.18,30.25 5.96,30.25 5.84,30.14 5.84,28.99 5.55,28.7 5.07,28.7 4.77,28.99 4.77,30.01 4.64,30.15 4.43,30.15 4.32,30.04 4.32,28.98 4.04,28.7 3.55,28.7 3.2,29.05 3.2,29.82 2.98,30.04 2.76,30.04 2.59,29.87 2.59,27.64 0.91,25.96 0.91,22.89 1.42,22.38 1.93,22.38 v2(2.03,22.48)
  BOTTOM w0.114: J1.4 2.8,22.46 2.7,22.36 2.15,22.36 v2(2.03,22.48)
C_PCIE_NVM_RX0_P: length 22.3
  TOP w0.114: v2(2.01,21.95) 1.88,22.07 1.3,22.07 0.61,22.76 0.61,26.09 2.29,27.76 2.29,30 2.64,30.35 3.1,30.35 3.51,29.95 3.51,29.18 3.68,29.01 3.89,29.01 3.99,29.11 3.99,30.16 4.28,30.45 4.76,30.45 5.08,30.14 5.08,29.12 5.19,29.01 5.42,29.01 5.54,29.12 5.54,30.26 5.83,30.56 6.31,30.56 6.6,30.26 6.6,29.35 6.72,29.23 7.02,29.23 R2.2
  BOTTOM w0.114: v2(2.01,21.95) 2.11,22.05 2.74,22.05 2.83,21.96 J1.2
C_PCIE_NVM_RX1_N: length 11.6
  TOP w0.114: v2(2.32,24.08) 2.12,23.88 1.91,23.88 1.65,24.13 1.65,25.4 3.28,27.03 4.88,27.03 5.22,27.37 5.22,27.83 5.36,27.97 5.77,27.97 5.92,27.81 5.92,26.98 6.35,26.54 6.99,26.54 R5.2
  BOTTOM w0.114: J1.8 3.32,23.88 2.52,23.88 v2(2.32,24.08)
C_PCIE_NVM_RX1_P: length 12.6
  TOP w0.114: v2(2.32,23.33) 2.08,23.57 1.78,23.57 1.35,24 1.35,25.53 3.15,27.33 4.75,27.33 4.91,27.5 4.91,27.95 5.23,28.27 5.89,28.27 6.22,27.94 6.22,27.1 6.48,26.85 6.92,26.85 R4.2
  BOTTOM w0.114: v2(2.32,23.33) 2.49,23.5 3.36,23.5 J1.6
C_PCIE_NVM_RX2_N: length 5
  TOP w0.114: v2(4.45,25.46) 4.45,24.89 5.05,24.28 6.97,24.28 R6.2
  BOTTOM w0.114: v2(4.45,25.46) 4.39,25.4 3.46,25.4 J1.12
C_PCIE_NVM_RX2_P: length 4.4
  TOP w0.114: v2(4.9,25.02) 4.93,24.99 4.93,24.84 5.18,24.59 6.94,24.59 R1.2
  BOTTOM w0.114: J1.10 3.46,25.02 v2(4.9,25.02)
C_PCIE_NVM_RX3_N: length 9.5
  TOP w0.114: v2(4.88,26.49) 4.88,26.43 4.43,25.98 3.99,25.98 3.81,25.81 3.81,23.7 5.19,22.31 6.95,22.31 R8.2
  BOTTOM w0.114: J1.16 4.41,26.96 v2(4.88,26.49)
C_PCIE_NVM_RX3_P: length 9
  TOP w0.114: R7.2 6.95,22.01 5.07,22.01 3.51,23.57 3.51,25.93 4.03,26.46 v2(4.32,26.46)
  BOTTOM w0.114: J1.14 v2(4.32,26.46)
C_PCIE_NVM_RX4_N: length 15.5
  TOP w0.114: v2(1.74,28.47) 1.64,28.37 1.35,28.37 1.02,28.7 1.02,32.87 6.16,38.01 6.95,38.01 R10.2
  BOTTOM w0.114: J1.20 2.51,28.46 2.41,28.36 1.85,28.36 v2(1.74,28.47)
C_PCIE_NVM_RX4_P: length 16.5
  TOP w0.114: R9.2 6.95,38.32 6.03,38.32 0.71,32.99 0.71,28.58 1.22,28.07 1.61,28.07 v2(1.74,27.94)
  BOTTOM w0.114: J1.18 2.51,27.96 2.41,28.05 1.85,28.05 v2(1.74,27.94)
C_PCIE_NVM_RX5_N: length 11
  TOP w0.114: v2(2.21,30.56) 2.08,30.68 2.08,32.79 5.02,35.73 6.95,35.73 R12.2
  BOTTOM w0.114: v2(2.21,30.56) 2.12,30.47 2.12,29.97 2.23,29.86 2.68,29.86 2.78,29.96 J1.24
C_PCIE_NVM_RX5_P: length 12.1
  TOP w0.114: v2(1.65,30.56) 1.78,30.68 1.78,32.92 4.89,36.03 6.95,36.03 R11.2
  BOTTOM w0.114: J1.22 2.75,29.46 2.65,29.55 2.01,29.55 1.82,29.74 1.82,30.39 v2(1.65,30.56)
C_PCIE_NVM_RX6_N: length 7.8
  TOP w0.114: v2(4.45,31.51) 4.28,31.34 4.01,31.34 3.43,31.93 3.43,32.89 3.98,33.44 6.95,33.44 R14.2
  BOTTOM w0.114: J1.28 3.49,31.37 3.96,31.37 4.1,31.51 v2(4.45,31.51)
C_PCIE_NVM_RX6_P: length 8.7
  TOP w0.114: R13.2 6.95,33.74 3.85,33.74 3.12,33.02 3.12,31.8 3.89,31.04 4.36,31.04 v2(4.45,30.96)
  BOTTOM w0.114: v2(4.45,30.96) 4.1,30.96 3.99,31.06 3.51,31.06 J1.26
C_PCIE_NVM_RX7_N: length 5.3
  TOP w0.114: R16.2 6.95,31.15 5.65,31.15 4.57,32.23 4.57,32.85 v2(4.47,32.96)
  BOTTOM w0.114: J1.32 v2(4.47,32.96)
C_PCIE_NVM_RX7_P: length 5.6
  TOP w0.114: v2(5.05,32.97) 4.88,32.79 4.88,32.36 5.78,31.46 6.95,31.46 R15.2
  BOTTOM w0.114: J1.30 4.55,32.46 4.88,32.79 4.88,32.8 v2(5.05,32.97)
C_PCIE_NVM_TX0_N: length 5.5
  BOTTOM w0.114: R79.1 14.86,22.73 14.46,22.33 10.31,22.33 10.18,22.46 J1.3
C_PCIE_NVM_TX0_P: length 5.5
  BOTTOM w0.114: R78.1 14.44,22.02 10.19,22.02 10.12,21.96 J1.1
C_PCIE_NVM_TX1_N: length 2.2
  BOTTOM w0.114: R81.1 11.17,23.86 10.3,23.86 10.21,23.96 J1.7
C_PCIE_NVM_TX1_P: length 2.2
  BOTTOM w0.114: R80.1 11.13,23.55 10.27,23.55 10.17,23.46 J1.5
C_PCIE_NVM_TX2_N: length 5.5
  BOTTOM w0.114: J1.11 10.18,25.46 10.28,25.36 14.44,25.36 14.86,25.77 R83.1
C_PCIE_NVM_TX2_P: length 5.5
  BOTTOM w0.114: R82.1 14.45,25.05 10.27,25.05 10.17,24.96 J1.9
C_PCIE_NVM_TX3_N: length 2.2
  BOTTOM w0.114: R85.1 11.12,26.86 10.28,26.86 10.18,26.96 J1.15
C_PCIE_NVM_TX3_P: length 2.2
  BOTTOM w0.114: J1.13 10.15,26.46 10.25,26.55 11.17,26.55 R84.1
C_PCIE_NVM_TX4_N: length 5.5
  BOTTOM w0.114: J1.19 10.15,28.46 10.25,28.36 14.4,28.36 R87.1
C_PCIE_NVM_TX4_P: length 5.5
  BOTTOM w0.114: J1.17 10.18,27.96 10.27,28.05 14.5,28.05 R86.1
C_PCIE_NVM_TX5_N: length 2.2
  BOTTOM w0.114: R89.1 11.07,29.86 10.56,29.86 10.46,29.96 J1.23
C_PCIE_NVM_TX5_P: length 2.2
  BOTTOM w0.114: J1.21 10.46,29.46 10.56,29.55 11.22,29.55 R88.1
C_PCIE_NVM_TX6_N: length 5.5
  BOTTOM w0.114: R91.1 14.36,31.37 10.39,31.37 10.3,31.46 9.57,31.46 J1.27
C_PCIE_NVM_TX6_P: length 5.5
  BOTTOM w0.114: R90.1 14.54,31.06 10.41,31.06 10.31,30.96 J1.25
C_PCIE_NVM_TX7_N: length 2.2
  BOTTOM w0.114: J1.31 10.46,32.96 10.56,32.86 11.15,32.86 R93.1
C_PCIE_NVM_TX7_P: length 2.2
  BOTTOM w0.114: R92.1 11.14,32.55 10.56,32.55 10.46,32.46 J1.29
CLK0_N: length 5.4
  TOP w0.114: v2(24.31,35.18) 24.21,35.08 24.21,34.24 23.79,33.82 21.88,33.82 21.78,33.72 J7.53
  BOTTOM w0.114: v2(24.31,35.18) 24.31,35.19 24.23,35.27 24.23,35.66 R37.1
CLK0_P: length 4.9
  TOP w0.114: v2(23.77,35.18) 23.9,35.05 23.9,34.37 23.66,34.12 21.88,34.12 21.79,34.22 J7.55
  BOTTOM w0.114: v2(23.77,35.18) 23.92,35.33 23.92,35.65 R40.1
CLK1_N: length 4.7
  TOP w0.114: R53.1 17.04,72.03 20.37,72.03 20.46,71.95 J8.53
CLK1_P: length 4.7
  TOP w0.114: R55.1 17.06,72.34 20.4,72.34 20.51,72.45 J8.55
CLK_32KHZ_1: length 1.4
  BOTTOM w0.152: R72.1 Y3.3
CLK_32KHZ_2: length 1.6
  BOTTOM w0.152: R73.1 Y4.3
CLKREQ#_1: length 60.2
  BOTTOM w0.152: R36.1 23.72,33.4 22.89,34.24 22.89,38.63 24.05,39.8 24.05,70.89 22.94,72.01 20.04,72.01 18.81,70.78 18.81,69.81 10.95,61.96 J1.81
CLKREQ#_2: length 42.2
  TOP w0.152: v2(8,72.34) 9.45,72.34 16.99,79.88 27.69,79.88 32.26,75.31 v2(32.26,73.91)
  BOTTOM w0.152: v2(32.26,73.91) R52.1 ; v2(8,72.34) 8,63.2 8.71,62.48 9.54,62.48 J1.83
DAS/LED2: length 3.7
  TOP w0.254: J8.10 v2(29.83,61.2)
  BOTTOM w0.254: v2(29.83,61.2) 30.58,61.2 R102.2 32.27,61.22 Q8.1
DAS/LED_1: length 4
  TOP w0.254: J7.10 v2(29.83,22.97)
  BOTTOM w0.254: v2(29.83,22.97) 30.84,22.97 R98.2 32.65,22.99 Q6.1
DEVSLP_1: length 112.5
  TOP w0.152: v2(31.75,28.7) 41.91,38.86 41.91,80.19 36.91,85.19 8.94,85.19 2.29,78.54 v2(2.29,68.46)
  BOTTOM w0.152: R99.1 31.74,28.71 ; 31.74,28.71 R70.1 ; 31.74,28.71 v2(31.75,28.7) ; J1.100 v2(2.29,68.46)
DEVSLP_2: length 38
  TOP w0.152: v2(31.74,67.61) 31.74,71.92 28.65,75.01 13.79,75.01 v2(7.49,68.71)
  BOTTOM w0.152: J1.98 5.35,67.96 6.1,68.71 v2(7.49,68.71) ; R103.1 v2(31.74,67.61) R71.1
HSMC_PWR_SENSE: length 156.9
  TOP w0.152: v2(8.48,73.89) 15.47,80.87 28.22,80.87 v2(37.97,71.12)
  BOTTOM w0.152: v2(8.48,73.89) 8.48,68.78 8.81,68.46 J1.99 ; v2(37.97,71.12) 45.21,63.88 146.27,63.88 J4.5
HSMC_RESET#: length 35.2
  BOTTOM w0.152: R77.1 35.82,64.14 33.64,64.14 Q3.1 33.5,64.13 R74.2 28.58,64.13 24.51,68.2 24.51,71.09 23.24,72.36 17.12,72.36 10.21,65.46 J1.91
OSC1_EN: length 80.8
  TOP w0.152: v2(5.21,71.48) 5.21,78.38 9.12,82.3 29.34,82.3 38.73,72.9 38.73,41.9 v2(37.85,41.01)
  BOTTOM w0.152: J1.108 5.19,71.46 v2(5.21,71.48) ; R68.2 v2(37.85,41.01)
OSC2_EN: length 46.1
  TOP w0.152: v2(36.58,79.24) 36.58,81.68 35.26,83.01 9.22,83.01 4.32,78.1 v2(4.32,70.94)
  BOTTOM w0.152: v2(4.32,70.94) 4.3,70.96 J1.106 ; R69.2 v2(36.58,79.24)
P_12V_HSMC_ON: length 165
  TOP w0.152: v2(8.64,67.94) 8.63,67.94 R62.2 7.37,67.94 6.71,68.6 6.71,72.62 7.35,73.25 9.19,73.25 16.31,80.37 27.97,80.37 v2(37.97,70.36) ; Q2.1 v2(139.57,31.44)
  BOTTOM w0.152: v2(139.57,31.44) 108.14,62.87 45.47,62.87 v2(37.97,70.36) ; J1.97 9.56,67.94 v2(8.64,67.94)
P_12V_ON:
  vias: v1(140.72,35.71) v1(140.79,37.87) v1(140.79,34.06) v1(141.94,36.98) v1(141.94,34.82)
PCIE1_SMBUS_ALERT: length 113
  TOP w0.152: v2(33.02,32.77) 34.85,32.77 41.15,39.07 41.15,80.21 36.65,84.71 9.32,84.71 3.17,78.56 3.17,63.29 v2(2.35,62.46)
  BOTTOM w0.152: J1.84 v2(2.35,62.46) ; R34.1 v2(33.02,32.77)
PCIE1_SMBUS_SCL: length 64.9
  TOP w0.152: v2(1.02,19.79) 10.17,10.64 22.83,10.64 24.76,12.57 24.76,27.79 27.45,30.47 J7.40 v2(30,30.47)
  BOTTOM w0.152: R29.1 30.73,30.47 v2(30,30.47) ; v2(1.02,19.79) R17.2
PCIE1_SMBUS_SDA: length 21.1
  TOP w0.152: v2(14.43,34.42) 16.76,36.75 23.7,36.75 24.76,35.69 24.76,33.78 v2(27.43,31.11) 27.58,30.97 J7.42
  BOTTOM w0.152: R18.2 v2(14.43,34.42) ; v2(27.43,31.11) R30.1
PCIE1_WAKE#: length 4.3
  TOP w0.152: J7.54 v2(27.69,33.97)
  BOTTOM w0.152: R35.1 R39.2 R38.2 27.49,33.97 v2(27.69,33.97)
PCIE1_WAKE#_HSE: length 114.6
  TOP w0.152: v2(25.27,34.54) 26.42,35.69 33.45,35.69 40.39,42.62 40.39,80.26 37.24,83.41 8.84,83.41 3.68,78.26 3.68,62.73 v2(4.45,61.96)
  BOTTOM w0.152: R38.1 v2(25.27,34.54) ; J1.82 v2(4.45,61.96)
PCIE2_SMBUS_ALERT: length 31.7
  TOP w0.152: v2(25.25,69.85) 24.46,70.64 24.46,72.19 24.43,72.21 24.43,72.26 22.43,74.27 14.17,74.27 9.53,69.62 9.53,65.91 7.57,63.96 v2(5.41,63.96)
  BOTTOM w0.152: J1.88 v2(5.41,63.96) ; R50.1 v2(25.25,69.85)
PCIE2_SMBUS_SCL: length 61.9
  TOP w0.152: J8.40 v2(27.57,68.7) 25,68.7 23.75,69.95 23.75,71.81 22.05,73.51 14.35,73.51 11.28,70.43 v2(11.28,58.98)
  BOTTOM w0.152: R45.1 26.92,68.7 v2(27.57,68.7) ; v2(11.28,58.98) 8.15,55.85 8.15,44.53 1.02,37.4 R19.2
PCIE2_SMBUS_SDA: length 60.1
  TOP w0.152: v2(29.97,69.34) 29.83,69.2 J8.42 25.24,69.2 24.13,70.31 24.13,72.09 22.25,73.96 14.3,73.96 10.79,70.46 v2(10.79,57.81)
  BOTTOM w0.152: R46.1 v2(29.97,69.34) ; v2(10.79,57.81) 12.57,56.04 R20.2
PCIE2_WAKE#: length 4.1
  TOP w0.152: v2(27.56,72.2) J8.54
  BOTTOM w0.152: R56.2 R51.1 R54.2 26.98,72.2 v2(27.56,72.2)
PCIE2_WAKE#_HSE: length 31
  TOP w0.152: v2(4.93,63.37) 4.93,64.21 5.18,64.47 7.57,64.47 9.14,66.04 9.14,69.85 13.92,74.63 22.78,74.63 v2(25.27,72.14)
  BOTTOM w0.152: v2(4.93,63.37) 4.84,63.46 J1.86 ; R54.1 v2(25.27,72.14)
PCIE_CG1_HSMC_CLK0_N: length 44.7
  TOP w0.114: R22.1 3.71,55.84 4.51,55.84 v2(4.64,55.97) ; v2(24.28,37.97) 24.17,38.09 24.17,41.67 18.57,47.27 18.57,60.07 18.06,60.58 17.64,60.58 v2(17.53,60.69)
  BOTTOM w0.114: v2(24.28,37.97) 24.18,37.87 24.18,37.53 R37.2 ; J1.80 4.29,55.96 4.38,55.87 4.54,55.87 v2(4.64,55.97) 4.75,55.86 6.74,55.86 11.46,60.58 17.41,60.58 v2(17.53,60.69)
PCIE_CG1_HSMC_CLK0_P: length 45.1
  TOP w0.114: v2(4.64,55.44) 4.54,55.54 3.71,55.54 R24.1 ; v2(23.75,37.97) 23.86,38.09 23.86,41.54 18.26,47.14 18.26,59.94 17.93,60.27 17.64,60.27 v2(17.53,60.16)
  BOTTOM w0.114: v2(23.75,37.97) 23.88,37.85 23.88,37.46 R40.2 ; J1.78 4.29,55.46 4.38,55.54 4.54,55.54 v2(4.64,55.44) 4.75,55.55 6.86,55.55 11.58,60.27 15.08,60.27 15.2,60.16 15.2,60.03 15.31,59.92 15.54,59.92 15.66,60.03 15.66,60.16 15.77,60.27 16,60.27 16.11,60.16 16.11,60.03 16.23,59.92 16.46,59.92 16.57,60.03 16.57,60.16 16.68,60.27 17.41,60.27 v2(17.53,60.16)
PCIE_CG1_HSMC_CLK1_N: length 21.6
  TOP w0.114: R21.1 11.07,54.86 10.95,54.97 10.95,55.67 10.95,55.68 v2(10.95,55.92) 10.84,56.03 10.84,56.46 12.62,58.24 12.62,70.13 14.58,72.09 15.17,72.09 R53.2
  BOTTOM w0.114: J1.79 9.59,55.96 9.62,55.92 v2(10.95,55.92)
PCIE_CG1_HSMC_CLK1_P: length 21.7
  TOP w0.114: R23.1 10.54,55.36 v2(10.54,55.5) 10.54,55.75 10.53,55.75 10.53,56.58 12.32,58.37 12.32,70.26 14.45,72.39 15.25,72.39 R55.2
  BOTTOM w0.114: v2(10.54,55.5) 9.61,55.5 J1.77
PCIE_NVM_RX0_N: length 32.5
  TOP w0.114: R3.1 8.79,28.87 9.94,28.87 10.15,29.07 10.31,29.07 10.41,28.96 10.57,28.96 10.74,29.13 10.74,29.29 10.63,29.39 10.63,29.55 10.79,29.72 10.95,29.72 11.06,29.61 11.22,29.61 11.38,29.77 11.38,29.93 11.28,30.04 11.28,30.2 12.12,31.04 12.12,32 13.28,33.17 16.03,33.17 16.79,33.93 16.79,35.62 16.93,35.76 17.13,35.76 17.25,35.65 17.25,31.11 17.54,30.82 18.02,30.82 18.34,31.14 18.34,35.65 18.45,35.76 18.65,35.76 18.77,35.65 18.77,31.11 19.06,30.82 20.39,30.82 20.48,30.72 J7.41
PCIE_NVM_RX0_P: length 31.5
  TOP w0.114: J7.43 20.48,31.22 20.38,31.12 19.19,31.12 19.07,31.24 19.07,35.78 18.78,36.07 18.33,36.07 18.03,35.78 18.03,31.26 17.89,31.12 17.69,31.12 17.58,31.24 17.58,35.78 17.28,36.07 16.8,36.07 16.48,35.75 16.48,34.06 15.9,33.48 13.16,33.48 11.81,32.13 11.81,31.17 9.82,29.17 8.79,29.17 R2.1
PCIE_NVM_RX1_N: length 42.1
  TOP w0.114: J7.29 20.49,27.72 20.41,27.8 19.4,27.8 19.1,28.09 19.1,29.74 18.96,29.88 18.76,29.88 18.65,29.76 18.65,28.09 18.35,27.8 17.87,27.8 17.55,28.12 17.55,29.76 17.44,29.88 17.24,29.88 17.12,29.76 17.12,28.09 16.83,27.8 16.33,27.8 16.04,28.09 16.04,32.13 15.93,32.24 15.7,32.24 15.58,32.13 15.58,28.09 15.29,27.8 14.81,27.8 14.52,28.09 14.52,32.13 14.4,32.24 14.18,32.24 14.06,32.13 14.06,28.09 13.77,27.8 13.24,27.8 12.94,28.09 12.94,29.69 12.8,29.83 12.6,29.83 12.49,29.72 12.49,28.09 12.19,27.8 11.51,27.8 11.39,27.69 11.39,27.57 11.25,27.43 11.05,27.43 10.94,27.55 10.94,27.69 10.82,27.8 10.4,27.8 9.86,27.26 9.86,27.1 9.97,27 9.97,26.83 9.81,26.67 9.65,26.67 9.54,26.78 9.38,26.78 9.18,26.58 8.79,26.58 R5.1
PCIE_NVM_RX1_P: length 41.2
  TOP w0.114: J7.31 20.47,28.22 20.36,28.11 19.52,28.11 19.41,28.22 19.41,29.86 19.09,30.18 18.61,30.18 18.32,29.89 18.32,28.22 18.2,28.11 18,28.11 17.86,28.25 17.86,29.89 17.57,30.18 17.11,30.18 16.82,29.89 16.82,28.22 16.7,28.11 16.46,28.11 16.35,28.22 16.35,32.25 16.05,32.54 15.57,32.54 15.28,32.25 15.28,28.22 15.17,28.11 14.94,28.11 14.82,28.22 14.82,32.25 14.53,32.54 14.05,32.54 13.76,32.25 13.76,28.22 13.64,28.11 13.36,28.11 13.25,28.22 13.25,29.82 12.93,30.14 12.48,30.14 12.18,29.85 12.18,28.22 12.07,28.11 10.28,28.11 9.06,26.89 8.79,26.89 R4.1
